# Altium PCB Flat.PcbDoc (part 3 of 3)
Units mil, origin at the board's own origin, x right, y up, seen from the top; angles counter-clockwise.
Board outline 3858.27 x 3228.35 mil, 2 copper layers (Top Layer, Bottom Layer); 95 components, 49 nets, 285 pads, 121 vias.
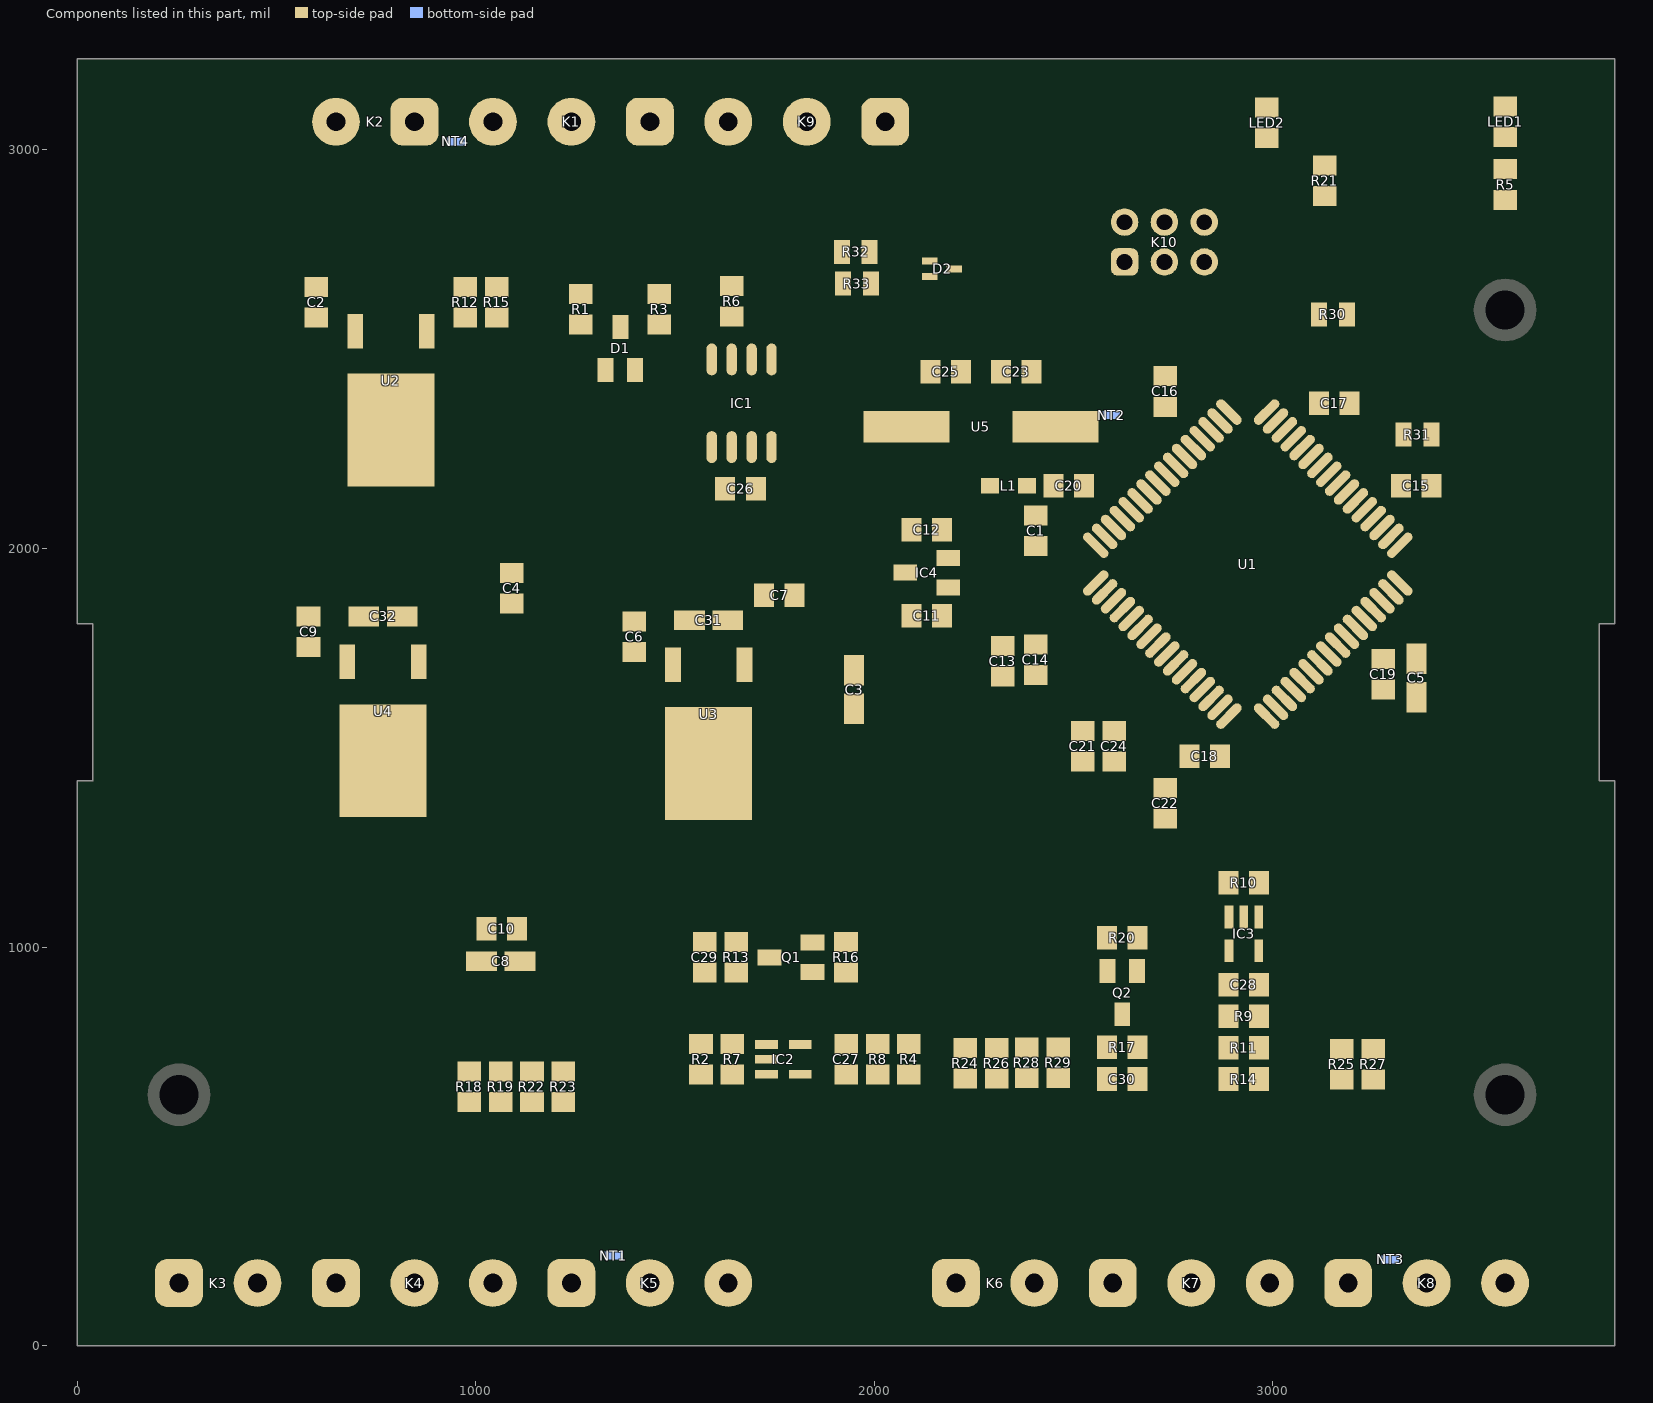
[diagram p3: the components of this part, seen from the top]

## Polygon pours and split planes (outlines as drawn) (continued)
QGND on Top Layer "Top Layer-No Net" (solid, pour order 2): 2039.79,2204.83 2524.68,2204.83 2524.68,2205.13 2592.56,2274.03 2591.76,2274.84 2591.76,2410.67 2511.1,2492.53 2010.69,2492.53 1933.11,2413.79 1933.11,2276 1933.11,2269.49 1992.65,2209.07 1996.83,2204.83 2001,2204.83

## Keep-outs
Keep-Out Layer:
  lines w7.87: 196.85,3228.35 949.37,3228.35 1011.71,3166.01 3779.53,3166.01 3779.53,0 0,0 0,1269.68 0,1359.39 39.37,1398.76 39.37,1829.8 0,1869.17 0,3025.5 0,3228.35 112.6,3228.35 196.85,3228.35 ; 196.85,3228.35 196.85,3228.35

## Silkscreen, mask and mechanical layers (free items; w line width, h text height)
Top Overlay:
  circle w20: c2627.95,2630.95 r10
  lines w19.68: 84.68,1717.95 84.68,3139.82 413.39,3139.82 413.39,1717.95 84.68,1717.95
  text "MCU" at 2742.59,3040.37 h60
  text "PWR" at 3365.54,3040.37 h60
  text "S1" at 1860.24,2800 h60 r90
  text "3.3V" at 2405.55,2796.88 h43.31
  text "GND" at 2913.39,2796.88 h43.31
  text "S2" at 2058.23,2786.05 h60 r90
  text "B" at 1475,2778.74 h60 r90
  text "A" at 1263.82,2775 h60 r90
  text "GND" at 1659.84,2724.23 h60 r90
  text "24V" at 684.36,2720.49 h60 r90
  text "GND" at 882.17,2720.49 h60 r90
  text "GND" at 1078.15,2720.49 h60 r90
  text "DATA" at 2397.68,2701.93 h43.31
  text "CLK" at 2913.39,2694.63 h43.31
  text "PDI" at 2732.59,2587.65 h60
  text "HVPSU v1.0" at 184.68,1742.95 h60 r90
  text "designed by Vid Berce" at 275.59,1742.84 h60 r90
  text "29.10.2013 (c) LPVO 2013" at 374.02,1742.84 h60 r90
  text "V_M" at 283.99,353.89 h60 r90
  text "I_M" at 483.4,353.89 h60 r90
  text "EN" at 693.69,353.89 h60 r90
  text "X" at 877.32,353.89 h60 r90
  text "ADJ" at 1068.83,353.89 h60 r90
  text "GND" at 1274.4,353.89 h60 r90
  text "GND" at 1472.11,353.89 h60 r90
  text "24V" at 1668.1,353.89 h60 r90
  text "V_M" at 2228.09,354.33 h60 r90
  text "I_M" at 2427.51,354.33 h60 r90
  text "EN" at 2637.8,354.33 h60 r90
  text "X" at 2821.42,354.33 h60 r90
  text "ADJ" at 3012.94,354.33 h60 r90
  text "GND" at 3218.5,354.33 h60 r90
  text "GND" at 3416.22,354.33 h60 r90
  text "24V" at 3612.2,354.33 h60 r90
Mechanical 1:
  lines w7.87: 39.37,1771.65 39.37,1417.32 ; 39.37,1417.32 0,1417.32 0,807.09 0,0 3858.27,0 3858.27,354.33 3858.27,1062.99 3858.27,1417.32 ; 39.37,1417.32 39.37,1811.02 0,1811.02 0,3228.35 3858.27,3228.35 3858.27,1811.02 3818.9,1811.02 3818.9,1417.32 ; 3818.9,1417.32 3858.27,1417.32 ; 3818.9,1417.32 3858.27,1417.32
